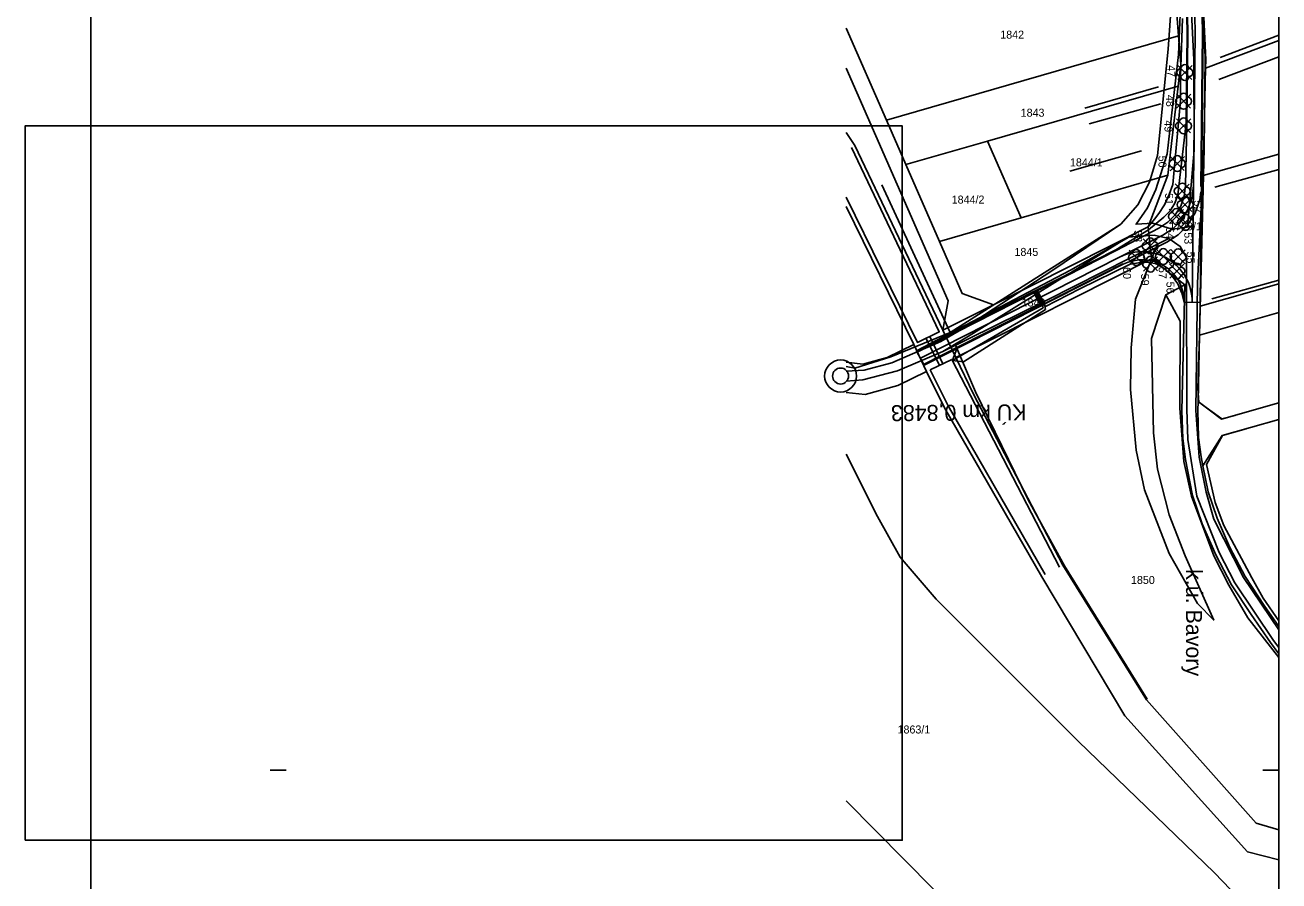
# Model space of a CAD drawing. Extents: x -601800 to -601487, y -1201912 to -1200862.
# Drawn here: x -601800.1 to -601486.7, y -1201730.1 to -1201516.2 of the extents above; entities that cross this region are included whole.
import ezdxf

# ---------------------------------------------------------------- set-up
doc = ezdxf.new("R2010")
doc.units = 0
for name, color, linetype in [('Hranice parcel', 7, 'Continuous'), ('Parcelní čísla', 7, 'Continuous'), ('popis', 7, 'Continuous'), ('u_hrany', 7, 'Continuous'), ('U_keř', 7, 'Continuous'), ('u_návrh', 7, 'Continuous'), ('u_osa', 7, 'Continuous'), ('u_popis katastru', 7, 'Continuous'), ('u_příčný odvodňovací žlab', 7, 'Continuous'), ('u_staniceni', 7, 'Continuous'), ('u_strom', 7, 'Continuous'), ('u_terénní úpravy', 7, 'Continuous'), ('x_rám', 7, 'Continuous')]:
    doc.layers.add(name, color=color, linetype=linetype)

msp = doc.modelspace()

# ---------------------------------------------------------------- linework, layer by layer
at = {"layer": 'Hranice parcel'}
for p, q in [((-601513.82, -1201491.91), (-601511.75, -1201518.89)), ((-601594.83, -1201516.98), (-601584.77, -1201539.96)), ((-601584.77, -1201539.96), (-601511.75, -1201518.89)), ((-601486.66, -1201520.06), (-601504.99, -1201526.96)), ((-601505.6, -1201553.8), (-601504.99, -1201526.96)), ((-601559.51, -1201545.16), (-601511.83, -1201531.46)), ((-601511.83, -1201531.46), (-601514.42, -1201553.71)), ((-601584.77, -1201539.96), (-601579.92, -1201551.03)), ((-601579.92, -1201551.03), (-601559.51, -1201545.16)), ((-601559.51, -1201545.16), (-601551.13, -1201564.33)), ((-601579.92, -1201551.03), (-601571.52, -1201570.23)), ((-601551.13, -1201564.33), (-601514.42, -1201553.71)), ((-601514.42, -1201553.71), (-601519.33, -1201566.6)), ((-601506.34, -1201586.43), (-601505.6, -1201553.8)), ((-601571.52, -1201570.23), (-601551.13, -1201564.33)), ((-601558.04, -1201586.08), (-601519.33, -1201566.6)), ((-601519.33, -1201566.6), (-601518.5, -1201574.62)), ((-601567.44, -1201599.25), (-601518.5, -1201574.62)), ((-601570.68, -1201592.44), (-601558.04, -1201586.08)), ((-601506.51, -1201593.65), (-601506.34, -1201586.43)), ((-601567.44, -1201599.25), (-601570.68, -1201592.44)), ((-601506.89, -1201610.28), (-601506.51, -1201593.65)), ((-601577.91, -1201595.98), (-601574.75, -1201602.78))]:
    msp.add_line(p, q, dxfattribs=at)
for points in [[(-601504.99, -1201526.96), (-601504.94, -1201524.87), (-601505.47, -1201514.18)], [(-601511.75, -1201518.89), (-601511.2, -1201526.06), (-601511.83, -1201531.46)], [(-601594.83, -1201526.97), (-601569.38, -1201585.08), (-601570.68, -1201592.44)], [(-601594.83, -1201543.05), (-601592.66, -1201546.3), (-601570.68, -1201592.44)], [(-601486.66, -1201548.47), (-601505.6, -1201553.8)], [(-601594.83, -1201561.49), (-601577.91, -1201595.98)], [(-601571.52, -1201570.23), (-601565.81, -1201583.28), (-601558.04, -1201586.08)], [(-601518.5, -1201574.62), (-601510.22, -1201581.07), (-601510.94, -1201612.53), (-601510.72, -1201619.53), (-601510.05, -1201624.75), (-601508.24, -1201633.75), (-601505.86, -1201640.82), (-601502.47, -1201648.58), (-601498.5, -1201656.04), (-601493.62, -1201663.46), (-601488.75, -1201670.45), (-601486.66, -1201673.28)], [(-601486.66, -1201580.87), (-601506.34, -1201586.43)], [(-601486.66, -1201588.04), (-601506.51, -1201593.65)], [(-601577.91, -1201595.98), (-601584.57, -1201599.24), (-601590.66, -1201600.91), (-601594.83, -1201600.45)], [(-601486.66, -1201717.3), (-601492.39, -1201715.61), (-601519.73, -1201684.8), (-601540.64, -1201651.14), (-601563.05, -1201608.38), (-601567.44, -1201599.25)], [(-601574.75, -1201602.78), (-601581.91, -1201606.29), (-601590.06, -1201608.52), (-601594.83, -1201607.99)], [(-601574.75, -1201602.78), (-601570.23, -1201611.8), (-601545.97, -1201654.03), (-601525.15, -1201688.8), (-601494.52, -1201722.78), (-601486.66, -1201724.8)], [(-601505.66, -1201626.3), (-601506.1, -1201624.1), (-601506.73, -1201619.21), (-601506.94, -1201612.51), (-601506.89, -1201610.28)], [(-601486.66, -1201610.58), (-601501.05, -1201614.65), (-601506.89, -1201610.28)], [(-601486.66, -1201614.74), (-601500.81, -1201618.74), (-601505.66, -1201626.3)], [(-601594.83, -1201623.4), (-601587.01, -1201639.02), (-601581.31, -1201649.12), (-601572.35, -1201659.63), (-601536.87, -1201695.11), (-601502.76, -1201728.06), (-601486.66, -1201744.77)], [(-601486.66, -1201666.45), (-601490.31, -1201661.22), (-601495.06, -1201653.99), (-601498.9, -1201646.76), (-601502.13, -1201639.37), (-601504.35, -1201632.81), (-601505.66, -1201626.3)], [(-601594.83, -1201710.03), (-601507.63, -1201798.25)]]:
    msp.add_lwpolyline(points, dxfattribs=at)
at = {"layer": 'u_hrany'}
for points in [[(-601512.26, -1201390.52), (-601510.47, -1201401.41), (-601510.09, -1201413.72), (-601511.79, -1201441.97), (-601511.82, -1201455.52), (-601508.66, -1201487.01), (-601505.94, -1201512.07), (-601505.14, -1201523.95), (-601505.37, -1201547.09), (-601506.1, -1201561.67), (-601507, -1201580.71), (-601507.44, -1201612.51), (-601506.59, -1201624.18), (-601504.84, -1201632.93)], [(-601509.48, -1201566.66), (-601507.81, -1201547.43), (-601507.95, -1201524.83), (-601508.61, -1201511.46), (-601509.72, -1201499.44)], [(-601514.34, -1201522.2), (-601513.15, -1201505.52)], [(-601511, -1201505.42), (-601511.8, -1201523.53)], [(-601501.36, -1201524.25), (-601486.66, -1201518.72)], [(-601517.05, -1201548.75), (-601514.34, -1201522.2)], [(-601511.8, -1201523.53), (-601514.64, -1201548.39)], [(-601501.69, -1201529.78), (-601486.66, -1201524.09)], [(-601516.77, -1201531.63), (-601535.18, -1201536.93)], [(-601516.2, -1201535.84), (-601534.1, -1201540.88)], [(-601593.53, -1201546.79), (-601571.58, -1201592.88), (-601577.01, -1201595.54), (-601594.83, -1201559.22)], [(-601521.05, -1201547.61), (-601538.91, -1201552.71)], [(-601509.48, -1201566.66), (-601513.31, -1201567.15), (-601518.19, -1201565.68), (-601522.39, -1201565.97), (-601519.52, -1201561.86), (-601517.42, -1201557.27), (-601514.64, -1201548.39)], [(-601506.52, -1201593.72), (-601505.37, -1201547.09)], [(-601517.05, -1201548.75), (-601518.98, -1201555.47), (-601521.95, -1201561.09), (-601526.18, -1201565.91), (-601543.22, -1201577.44), (-601564.63, -1201591.39), (-601571.15, -1201595.24), (-601583.39, -1201600.55), (-601590.31, -1201602.43), (-601594.83, -1201602.65)], [(-601502.71, -1201556.7), (-601486.66, -1201552.25)], [(-601568.87, -1201592.97), (-601585.89, -1201556.1)], [(-601583.7, -1201599.06), (-601568.87, -1201592.97), (-601526.18, -1201565.91)], [(-601594.83, -1201605.18), (-601590.64, -1201604.85), (-601581.97, -1201602.55), (-601570.67, -1201597.77), (-601563.01, -1201593.18), (-601542.69, -1201580.51), (-601524.37, -1201569.19), (-601517.89, -1201568.67), (-601514.2, -1201569.51), (-601511.31, -1201571.5), (-601509.75, -1201574.25)], [(-601514.2, -1201569.51), (-601517.03, -1201570.93), (-601522.49, -1201584.67), (-601523.6, -1201596.8), (-601523.78, -1201607.28), (-601522.35, -1201622.38), (-601520.26, -1201632.29), (-601514.11, -1201648.21), (-601507.05, -1201660.77), (-601502.96, -1201664.86), (-601510.13, -1201648.82), (-601514.08, -1201638.6), (-601517, -1201627.14), (-601517.98, -1201618.06), (-601518.55, -1201594.5), (-601514.93, -1201583.59), (-601509.76, -1201580.82)], [(-601570.67, -1201597.77), (-601544.7, -1201584.94), (-601517.03, -1201570.93)], [(-601507.17, -1201633.88), (-601509.44, -1201619.72), (-601509.7, -1201612.19), (-601509.76, -1201580.82), (-601509.75, -1201574.25)], [(-601503.47, -1201584.58), (-601486.66, -1201579.96)], [(-601514.93, -1201583.59), (-601511.33, -1201590.16), (-601511.4, -1201611.89), (-601510.42, -1201625.27), (-601508.49, -1201633.89)], [(-601500.93, -1201614.59), (-601506.68, -1201610.38), (-601506.9, -1201607.04), (-601506.52, -1201593.72)], [(-601567.51, -1201596.21), (-601562.55, -1201607.8), (-601549.33, -1201634.79), (-601540.29, -1201651.32), (-601519.62, -1201684.67)], [(-601594.83, -1201601.47), (-601592.67, -1201601.9), (-601583.7, -1201599.06)], [(-601573.85, -1201602.35), (-601568.4, -1201599.72), (-601541.51, -1201651.64)], [(-601545.11, -1201653.52), (-601569.35, -1201611.33), (-601573.85, -1201602.35)], [(-601497.57, -1201613.76), (-601500.93, -1201614.59)], [(-601500.77, -1201618.77), (-601494.85, -1201617.12)], [(-601486.66, -1201665.08), (-601490.59, -1201659.41), (-601493.47, -1201654.35), (-601500.4, -1201641.28), (-601502.56, -1201635.52), (-601504.77, -1201626.02), (-601500.77, -1201618.77)], [(-601486.66, -1201667.3), (-601495.49, -1201654.25), (-601502.92, -1201639.69), (-601504.84, -1201632.93)], [(-601502.92, -1201648.81), (-601508.49, -1201633.89)], [(-601507.17, -1201633.88), (-601501.63, -1201648), (-601497.69, -1201655.55), (-601488, -1201669.96), (-601486.66, -1201671.73)], [(-601502.92, -1201648.81), (-601499.15, -1201656.12), (-601494.42, -1201664.28), (-601486.66, -1201674.2)]]:
    msp.add_lwpolyline(points, dxfattribs=at)
at = {"layer": 'U_keř'}
for p, q in [((-601511.96, -1201526.25), (-601508.43, -1201529.78)), ((-601508.39, -1201526.28), (-601511.93, -1201529.82)), ((-601512.29, -1201533.39), (-601508.75, -1201536.93)), ((-601508.72, -1201533.43), (-601512.25, -1201536.96)), ((-601512.29, -1201539.57), (-601508.75, -1201543.1)), ((-601508.72, -1201539.6), (-601512.25, -1201543.14)), ((-601513.87, -1201548.99), (-601510.34, -1201552.53)), ((-601510.3, -1201549.03), (-601513.84, -1201552.57)), ((-601512.63, -1201555.86), (-601509.09, -1201559.4)), ((-601509.06, -1201555.9), (-601512.59, -1201559.43)), ((-601511.93, -1201559.28), (-601508.4, -1201562.81)), ((-601508.36, -1201559.31), (-601511.9, -1201562.85)), ((-601514.07, -1201562.2), (-601510.53, -1201565.74)), ((-601510.5, -1201562.24), (-601514.03, -1201565.78)), ((-601511.82, -1201563.67), (-601508.28, -1201567.21)), ((-601508.25, -1201563.71), (-601511.78, -1201567.24)), ((-601520.64, -1201569.56), (-601517.1, -1201573.1)), ((-601517.07, -1201569.6), (-601520.6, -1201573.13)), ((-601524.08, -1201572.47), (-601520.55, -1201576.01)), ((-601520.51, -1201572.51), (-601524.05, -1201576.04)), ((-601517.34, -1201572.21), (-601513.8, -1201575.75)), ((-601513.77, -1201572.25), (-601517.3, -1201575.78)), ((-601513.65, -1201572.28), (-601510.11, -1201575.81)), ((-601510.08, -1201572.31), (-601513.61, -1201575.85)), ((-601520.56, -1201574.09), (-601517.02, -1201577.63)), ((-601516.98, -1201574.13), (-601520.52, -1201577.66)), ((-601514, -1201575.85), (-601510.47, -1201579.39)), ((-601510.43, -1201575.89), (-601513.97, -1201579.42))]:
    msp.add_line(p, q, dxfattribs=at)
for centre in [(-601512.07, -1201550.8), (-601510.13, -1201561.08), (-601510.01, -1201565.48), (-601518.84, -1201571.37), (-601518.75, -1201575.9), (-601511.84, -1201574.08)]:
    msp.add_circle(centre, 0.1, dxfattribs=at)
for centre, start, end in [((-601513.07, -1201550.8), 90, 270), ((-601512.07, -1201549.8), 0, 180), ((-601512.07, -1201551.8), 180, 0), ((-601511.07, -1201550.8), 270, 90), ((-601511.13, -1201561.08), 90, 270), ((-601510.13, -1201560.08), 0, 180), ((-601509.13, -1201561.08), 270, 90), ((-601510.13, -1201562.08), 180, 0), ((-601510.01, -1201564.48), 0, 180), ((-601511.01, -1201565.48), 90, 270), ((-601510.01, -1201566.48), 180, 0), ((-601509.01, -1201565.48), 270, 90), ((-601519.84, -1201571.37), 90, 270), ((-601518.84, -1201570.37), 0, 180), ((-601517.84, -1201571.37), 270, 90), ((-601518.84, -1201572.37), 180, 0), ((-601512.84, -1201574.08), 90, 270), ((-601511.84, -1201573.08), 0, 180), ((-601510.84, -1201574.08), 270, 90), ((-601519.75, -1201575.9), 90, 270), ((-601518.75, -1201574.9), 0, 180), ((-601518.75, -1201576.9), 180, 0), ((-601517.75, -1201575.9), 270, 90), ((-601511.84, -1201575.08), 180, 0)]:
    msp.add_arc(centre, 1, start, end, dxfattribs=at)
at = {"layer": 'u_návrh'}
for p, q in [((-601506.04, -1201556.51), (-601506.35, -1201585.45)), ((-601506.35, -1201585.45), (-601510.36, -1201585.48)), ((-601571.55, -1201601.24), (-601574.82, -1201594.47)), ((-601570.65, -1201600.81), (-601573.92, -1201594.03)), ((-601577.24, -1201597.68), (-601575.36, -1201601.21))]:
    msp.add_line(p, q, dxfattribs=at)
for points in [[(-601549.75, -1201316.3), (-601549.39, -1201317.23), (-601542.68, -1201332.11), (-601535.16, -1201346.59), (-601526.84, -1201360.67), (-601522.55, -1201367.52), (-601519.89, -1201372.13), (-601517.56, -1201376.95), (-601515.6, -1201381.93), (-601514.03, -1201387.02), (-601512.87, -1201391.36), (-601511.61, -1201396.91), (-601510.79, -1201402.59), (-601510.43, -1201408.32), (-601510.53, -1201414.01), (-601512.26, -1201444.39), (-601512.42, -1201450.21), (-601512.24, -1201456), (-601511.71, -1201461.79), (-601506.5, -1201504.96), (-601506.06, -1201509.37), (-601505.82, -1201513.81), (-601505.77, -1201518.24), (-601506.19, -1201556.5)], [(-601553.14, -1201317.8), (-601552.81, -1201318.66), (-601546.01, -1201333.72), (-601538.39, -1201348.39), (-601530, -1201362.6), (-601525.72, -1201369.43), (-601523.16, -1201373.86), (-601520.96, -1201378.43), (-601519.1, -1201383.16), (-601517.59, -1201388.04), (-601516.46, -1201392.25), (-601515.25, -1201397.59), (-601514.48, -1201402.97), (-601514.13, -1201408.4), (-601514.23, -1201413.88), (-601515.96, -1201444.23), (-601516.12, -1201450.21), (-601515.93, -1201456.22), (-601515.39, -1201462.18), (-601510.17, -1201505.36), (-601509.75, -1201509.65), (-601509.52, -1201513.93), (-601509.47, -1201518.24), (-601509.71, -1201540.62)], [(-601515.46, -1201381.89), (-601513.89, -1201386.98), (-601512.72, -1201391.32), (-601511.46, -1201396.89), (-601510.64, -1201402.58), (-601510.28, -1201408.31), (-601510.38, -1201414.02), (-601512.11, -1201444.4), (-601512.27, -1201450.21), (-601512.09, -1201455.99), (-601511.56, -1201461.78), (-601506.35, -1201504.94), (-601505.91, -1201509.36), (-601505.67, -1201513.81), (-601505.62, -1201518.24), (-601506.04, -1201556.51)], [(-601519.24, -1201383.21), (-601517.73, -1201388.09), (-601516.61, -1201392.28), (-601515.4, -1201397.61), (-601514.63, -1201402.99), (-601514.28, -1201408.41), (-601514.38, -1201413.87), (-601516.11, -1201444.23), (-601516.27, -1201450.21), (-601516.08, -1201456.23), (-601515.54, -1201462.2), (-601510.32, -1201505.38), (-601509.9, -1201509.66), (-601509.67, -1201513.94), (-601509.62, -1201518.24), (-601509.86, -1201540.61)], [(-601509.86, -1201540.61), (-601511.93, -1201558.58), (-601512.67, -1201560.7), (-601513.86, -1201562.61), (-601515.44, -1201564.22), (-601519.25, -1201567.35), (-601527.41, -1201572.39)], [(-601509.71, -1201540.62), (-601510.03, -1201556.25), (-601510.36, -1201558.94), (-601511.22, -1201561.4), (-601512.59, -1201563.61), (-601514.41, -1201565.47), (-601516.68, -1201566.95), (-601527.34, -1201572.52)], [(-601506.2, -1201557.88), (-601506.44, -1201559.86), (-601507.59, -1201563.14), (-601509.43, -1201566.09), (-601511.86, -1201568.58), (-601514.68, -1201570.42), (-601524.04, -1201575.17)], [(-601527.41, -1201572.39), (-601577.23, -1201597.68)], [(-601527.34, -1201572.52), (-601547.96, -1201582.99)], [(-601525.6, -1201575.97), (-601575.36, -1201601.21)], [(-601525.67, -1201575.83), (-601545.37, -1201585.82)], [(-601547.91, -1201583.08), (-601577.12, -1201597.9)], [(-601546.33, -1201586.2), (-601575.48, -1201600.99)]]:
    msp.add_lwpolyline(points, dxfattribs=at)
msp.add_arc((-601520.85, -1201585.33), 10.5, 359.1692, 116.9057, dxfattribs=at)
at = {"layer": 'u_osa'}
msp.add_line((-601508.04, -1201556.38), (-601508.35, -1201585.46), dxfattribs=at)
msp.add_lwpolyline([(-601517.35, -1201382.55), (-601515.81, -1201387.53), (-601514.66, -1201391.8), (-601513.43, -1201397.25), (-601512.63, -1201402.78), (-601512.28, -1201408.36), (-601512.38, -1201413.95), (-601514.11, -1201444.31), (-601514.27, -1201450.21), (-601514.08, -1201456.11), (-601513.55, -1201461.99), (-601508.33, -1201505.16), (-601507.91, -1201509.51), (-601507.67, -1201513.87), (-601507.62, -1201518.24), (-601508.04, -1201556.38), (-601508.4, -1201559.4), (-601509.41, -1201562.27), (-601511.01, -1201564.85), (-601513.14, -1201567.02), (-601515.68, -1201568.69), (-601576.3, -1201599.45)], dxfattribs=at)
msp.add_arc((-601520.85, -1201585.33), 12.5, 359.3745, 116.9057, dxfattribs=at)
at = {"layer": 'u_příčný odvodňovací žlab'}
for points in [[(-601546.22, -1201586.43), (-601547.12, -1201584.64), (-601548.03, -1201582.86)], [(-601545.99, -1201586.31), (-601546.9, -1201584.53), (-601547.74, -1201582.88)], [(-601545.9, -1201586.27), (-601546.81, -1201584.48), (-601547.65, -1201582.83)], [(-601545.61, -1201586.12), (-601546.52, -1201584.33), (-601547.35, -1201582.68)], [(-601545.52, -1201586.07), (-601546.43, -1201584.29), (-601547.26, -1201582.64)], [(-601545.3, -1201585.96), (-601546.2, -1201584.17), (-601547.04, -1201582.52)]]:
    msp.add_lwpolyline(points, dxfattribs=at)
at = {"layer": 'u_staniceni'}
for radius in [4, 2]:
    msp.add_circle((-601596.23, -1201603.88), radius, dxfattribs=at)
at = {"layer": 'u_strom'}
msp.add_lwpolyline([(-601800.1, -1201719.92), (-601580.84, -1201719.92), (-601580.84, -1201541.36), (-601800.1, -1201541.36)], close=True, dxfattribs=at)
for centre in [(-601510.16, -1201528.05), (-601510.48, -1201535.2), (-601510.48, -1201541.37), (-601510.83, -1201557.66), (-601512.26, -1201564.01), (-601522.28, -1201574.28), (-601515.53, -1201574.02), (-601512.2, -1201577.66)]:
    msp.add_circle(centre, 0.1, dxfattribs=at)
for centre, start, end in [((-601510.16, -1201527.05), 0, 180), ((-601511.16, -1201528.05), 90, 270), ((-601510.16, -1201529.05), 180, 0), ((-601509.16, -1201528.05), 270, 90), ((-601511.48, -1201535.2), 90, 270), ((-601510.48, -1201534.2), 0, 180), ((-601509.48, -1201535.2), 270, 90), ((-601510.48, -1201536.2), 180, 0), ((-601511.48, -1201541.37), 90, 270), ((-601510.48, -1201540.37), 0, 180), ((-601510.48, -1201542.37), 180, 0), ((-601509.48, -1201541.37), 270, 90), ((-601511.83, -1201557.66), 90, 270), ((-601510.83, -1201556.66), 0, 180), ((-601509.83, -1201557.66), 270, 90), ((-601510.83, -1201558.66), 180, 0), ((-601513.26, -1201564.01), 90, 270), ((-601512.26, -1201563.01), 0, 180), ((-601511.26, -1201564.01), 270, 90), ((-601512.26, -1201565.01), 180, 0), ((-601523.28, -1201574.28), 90, 270), ((-601522.28, -1201573.28), 0, 180), ((-601521.28, -1201574.28), 270, 90), ((-601516.53, -1201574.02), 90, 270), ((-601515.53, -1201573.02), 0, 180), ((-601514.53, -1201574.02), 270, 90), ((-601522.28, -1201575.28), 180, 0), ((-601515.53, -1201575.02), 180, 0), ((-601513.2, -1201577.66), 90, 270), ((-601512.2, -1201576.66), 0, 180), ((-601511.2, -1201577.66), 270, 90), ((-601512.2, -1201578.66), 180, 0)]:
    msp.add_arc(centre, 1, start, end, dxfattribs=at)
at = {"layer": 'u_terénní úpravy'}
for p, q in [((-601545.76, -1201586.19), (-601545.59, -1201586.88)), ((-601545.3, -1201585.96), (-601544.99, -1201587.24)), ((-601567.15, -1201597.05), (-601568.27, -1201599.96)), ((-601568.27, -1201599.97), (-601565.54, -1201600.34))]:
    msp.add_line(p, q, dxfattribs=at)
for points in [[(-601515.18, -1201381.79), (-601513.5, -1201386.77), (-601512.27, -1201391.07), (-601511.36, -1201394.46), (-601510.89, -1201396.94), (-601510.1, -1201401.3), (-601509.88, -1201408.41), (-601509.86, -1201414.92), (-601511.16, -1201434.93), (-601511.79, -1201442.27), (-601511.95, -1201449.35), (-601511.81, -1201454.7), (-601511.82, -1201455.51), (-601511.2, -1201461.7), (-601509.62, -1201474.39), (-601508.62, -1201486.14), (-601507.39, -1201494.24), (-601506.28, -1201504.86), (-601505.75, -1201510), (-601505.46, -1201514.4), (-601505.14, -1201523.95), (-601505.17, -1201535.09), (-601505.65, -1201556.08), (-601506.35, -1201585.45)], [(-601510.74, -1201514.55), (-601511.19, -1201526.6), (-601511.29, -1201528.95), (-601511.23, -1201535.02), (-601513.15, -1201556), (-601514.13, -1201558.52), (-601515.24, -1201561.13), (-601516.66, -1201563.29), (-601517.73, -1201564.66), (-601519.33, -1201566.6), (-601521.68, -1201567.78), (-601538.8, -1201577.41), (-601577.28, -1201597.59)], [(-601510.36, -1201585.48), (-601510.94, -1201583.16), (-601511.91, -1201580.87), (-601513.23, -1201579.02), (-601515.17, -1201577.21), (-601516.81, -1201576.09), (-601517.62, -1201575.78), (-601519.8, -1201575.47), (-601521.74, -1201575.57), (-601523.81, -1201575.97), (-601536.41, -1201582.12), (-601545.15, -1201586.6)], [(-601545.59, -1201586.88), (-601568.27, -1201599.97)], [(-601565.54, -1201600.34), (-601544.99, -1201587.24)]]:
    msp.add_lwpolyline(points, dxfattribs=at)
at = {"layer": 'x_rám'}
for p, q in [((-601734.8, -1201702.35), (-601738.84, -1201702.35)), ((-601486.66, -1201702.35), (-601490.7, -1201702.35))]:
    msp.add_line(p, q, dxfattribs=at)
msp.add_lwpolyline([(-601486.66, -1200862.35), (-601486.66, -1201912.35), (-601783.66, -1201912.35), (-601783.66, -1200862.35)], close=True, dxfattribs=at)

# ---------------------------------------------------------------- texts
at = {"layer": 'Parcelní čísla'}
for s, p in [('1842', (-601556.32, -1201519.57)), ('1843', (-601551.22, -1201539.08)), ('1844/1', (-601538.9, -1201551.49)), ('1844/2', (-601568.46, -1201560.79)), ('1729/1', (-601514.09, -1201567.48)), ('1845', (-601552.77, -1201573.87)), ('1849', (-601550.99, -1201586.5)), ('1850', (-601523.64, -1201655.85)), ('1863/1', (-601582, -1201693.22))]:
    msp.add_text(s, height=2, dxfattribs=at).set_placement(p)
at = {"layer": 'popis'}
for s, p in [('47', (-601514.57, -1201526.19)), ('48', (-601514.85, -1201533.63)), ('49', (-601515.28, -1201539.98)), ('50', (-601516.78, -1201548.82)), ('51', (-601515.1, -1201558.16)), ('52', (-601507.95, -1201559.99)), ('54', (-601514.85, -1201566.65)), ('58', (-601522.87, -1201567.46)), ('53', (-601510.31, -1201567.97)), ('55', (-601509.72, -1201572.79)), ('60', (-601525.63, -1201576.67)), ('57', (-601516.72, -1201576.62)), ('59', (-601521.12, -1201578.31)), ('56', (-601514.78, -1201580.3))]:
    msp.add_text(s, height=2, rotation=270, dxfattribs=at).set_placement(p)
at = {"layer": 'u_popis katastru'}
msp.add_text('k.ú. Bavory', height=4, rotation=270, dxfattribs=at).set_placement((-601509.88, -1201652.14))
at = {"layer": 'u_staniceni'}
msp.add_text('KÚ km 0,8483', height=4, rotation=180.3558, dxfattribs=at).set_placement((-601549.77, -1201610.96))

doc.saveas('drawing.dxf')
